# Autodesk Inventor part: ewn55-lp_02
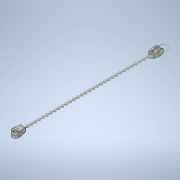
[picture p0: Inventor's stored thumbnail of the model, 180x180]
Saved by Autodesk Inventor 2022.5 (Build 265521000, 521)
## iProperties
Created: 2021-08
Part Number: ewn55-lp_02
Material: 一般
Document SubType Name: Modeling
Designer: ImaoCorp
Density: 1 g/cm^3
Appearance: 既定
Author: ImaoCorp
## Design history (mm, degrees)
feature "ewn55-lp_02"
node "ソリッド1"
